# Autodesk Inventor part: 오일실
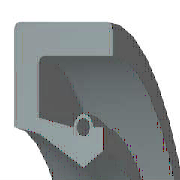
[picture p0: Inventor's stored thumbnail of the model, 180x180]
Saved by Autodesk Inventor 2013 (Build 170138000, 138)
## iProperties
Company: 한국ATC센터
IsCustomPart: 1
Created: 2009-02
Part Number: 오일실
Material: 고무
Description: 오일-실
Document SubType Name: Modeling
Standard: KS B 2804
Designer: KYOUNG IL JANG
Standards Organization: KS
Language: ko-KR
Size Designation: S - 12 22 7
Categories: <MemberInstance><Categories><Category DisplayName="샤프트 부품" InternalName="7f7aeb1f-a693-4053-b835-cee3144e0d98" Mnemonic="SHFT"><Category DisplayName="실링" Intern
Density: 0.93 g/cm^3
Mass: 1.0258 g
Surface Area: 17.5559 cm^2
Volume: 1.10301 cm^3
Vendor: CBT Solutions
Author: KYOUNG IL JANG
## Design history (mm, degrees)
revolve "본체" stored, may be unused: angle "d17" = 90 deg
revolve "스프링1" stored, may be unused: angle "d18" = 90 deg
body "Solid1"
sketch "스케치1"
  geometry: L1 (0, 11)-(7, 11); L2 (7, 11)-(7, 9.75); L3 (7, 9.75)-(1.75, 9.75); L4 (0, 11)-(0, 8.1); L5 (0, 8.1)-(1.75, 7.75); L6 (1.75, 7.75)-(4.9, 6); L7 (4.9, 6)-(0, 6); L8 (6.3, 6.875)-(6.3, 8.1); L9 (0, 0)-(9.586, 0) reference; L10 (4.9, 6)-(6.3, 6.875); L11 (0, 18)-(0, -3) reference; L12 (-1.917, 0)-(11.503, 0) reference; L13 (4.2, 8.1)-(1.75, 8.59); L14 (1.75, 8.59)-(1.75, 9.75); L15 (6.3, 8.1)-(5.6, 8.1); C1 r 0.455 at (4.9, 8.1); A1 r 0.7 centre (4.9, 8.1) between (5.6, 8.1) and (4.2, 8.1)
  constraints: 26 end point, 5 horizontal alignment, 4 perpendicular, 2 centre point, 2 collinear, 2 horizontal, 2 parallel, 2 point on circle, 2 point on line, 2 vertical alignment, 1 coincident
  dimensions: "d0" = 22 diameter of L1 L9 (= SD2); "d1" = 13.75 diameter of L8.start L9 (= ABDM); "d2" = 1.25 distance of L1.end L2.end (computed from SD); "d3" = 0.91 diameter of C1 (= SPDI); "d4" = 1.4 diameter of A1 (= SPDA); "d5" = 12 diameter of L6.end L9 (= NND); "d6" = 15.5 diameter of L5.end L9 (= TKDM); "d7" = 16.2 diameter of L4.end L9 (= HLDM); "d8" = 4.9 distance from line of C1.centre L4 (= SPDST); "d9" = 6.3 distance between parallel lines of L8 L4 (= SDI); "d10" = 7 distance between parallel lines of L2 L4 (= SWDT); "d12" = 1.75 distance between parallel lines of L14 L4 (= SD)
fillet "모깎기1" dims "d11" = 0.3 (= RR)
other parameters: "SD2" = 22 [user parameter; used in 1 equation term], "SWDT" = 7 [user parameter; used in 1 equation term], "RR" = 0.3 [user parameter; used in 1 equation term], "SD" = 1.75 [user parameter; used in 2 equation terms], "NND" = 12 [user parameter; used in 1 equation term], "SPDA" = 1.4 [user parameter; used in 1 equation term], "SPDI" = 0.91 [user parameter; used in 1 equation term], "TKDM" = 15.5 [user parameter; used in 1 equation term], "HLDM" = 16.2 [user parameter; used in 1 equation term], "ABDM" = 13.75 [user parameter; used in 1 equation term], "SDI" = 6.3 [user parameter; used in 1 equation term], "SPDST" = 4.9 [user parameter; used in 1 equation term], "d13" = 0, "d14" = 0, "d15" = 0, "LAB" = 0.35 [user parameter]
